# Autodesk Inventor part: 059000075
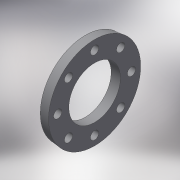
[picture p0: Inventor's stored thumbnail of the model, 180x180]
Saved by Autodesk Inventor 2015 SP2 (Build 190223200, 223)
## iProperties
Created: 2017-10
Part Number: 059000075
Material: Generic
Description: PLASSON BACKING FLANGE PVC 75
Document SubType Name: Modeling
Designer: KIM
Density: 1 g/cm^3
Appearance: Default
Author: KIM
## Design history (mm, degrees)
derived "059000.ipt"
feature "Solid1::059000.ipt"
tag "TaggingFeature1"
body "Solid1"
other parameters: "d0" = 19, "d1" = 94, "d2" = 185, "d3" = 181.3, "d5" = 18, "d6" = 72.5, "d7" = 19, "d8" = 0, "d10" = 360 deg, "D_" = 75, "E_" = 94, "E_1" = 185, "H_" = 19, "Dp_" = 145, "S_" = 18
